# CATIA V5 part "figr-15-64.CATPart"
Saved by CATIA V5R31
Part number: Part1
Bounding box of the stored display mesh (mm): x -10 to 10, y -10 to 10, z 0 to 26
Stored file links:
  D:\PROJECTS\Project 2021\US EDITION\CATIA V5 6R 2021\Resources\Part Files\c15_catia_v5_6r2021_prt\figr-15-64.CATPart
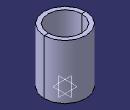
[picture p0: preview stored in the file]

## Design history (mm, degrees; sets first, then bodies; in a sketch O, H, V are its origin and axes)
SheetMetalParameters1: Thickness 2, BendRadius 4, KFactor 0.400515 {= log(min(100,max(20*SheetMetalParameters1.BendRadius,SheetMetalParameters1.Thickness)/SheetMetalParameters1.Thickness))/log(100)/2}, ReliefRadialLength 1, ReliefAxialLength 2, MinimumBendRadius 0
Body1 (main body)
  Sketch1 on xy-plane, origin (0, 0, 0), H (1, 0, 0), V (0, 1, 0)
    circle A1 centre (0, 0) radius 10
    radius A1 = 10
  d_RolledWall1: Extrude_Thickness 2, Extrude_Profile Sketch1, KFacteur 0.400515 {= SheetMetalParameters1.KFactor}, Extrude_StartLength 26, Extrude_EndLength 0, RolledWall_DeductionTable SheetMetalParameters1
